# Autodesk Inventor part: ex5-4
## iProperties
Created: 2006-03
Part Number: ex5-4
Document SubType Name: Modeling
Designer: Elise Moss
Author: Elise Moss
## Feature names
1. Extrusion1
2. Hole1
3. Hole2
